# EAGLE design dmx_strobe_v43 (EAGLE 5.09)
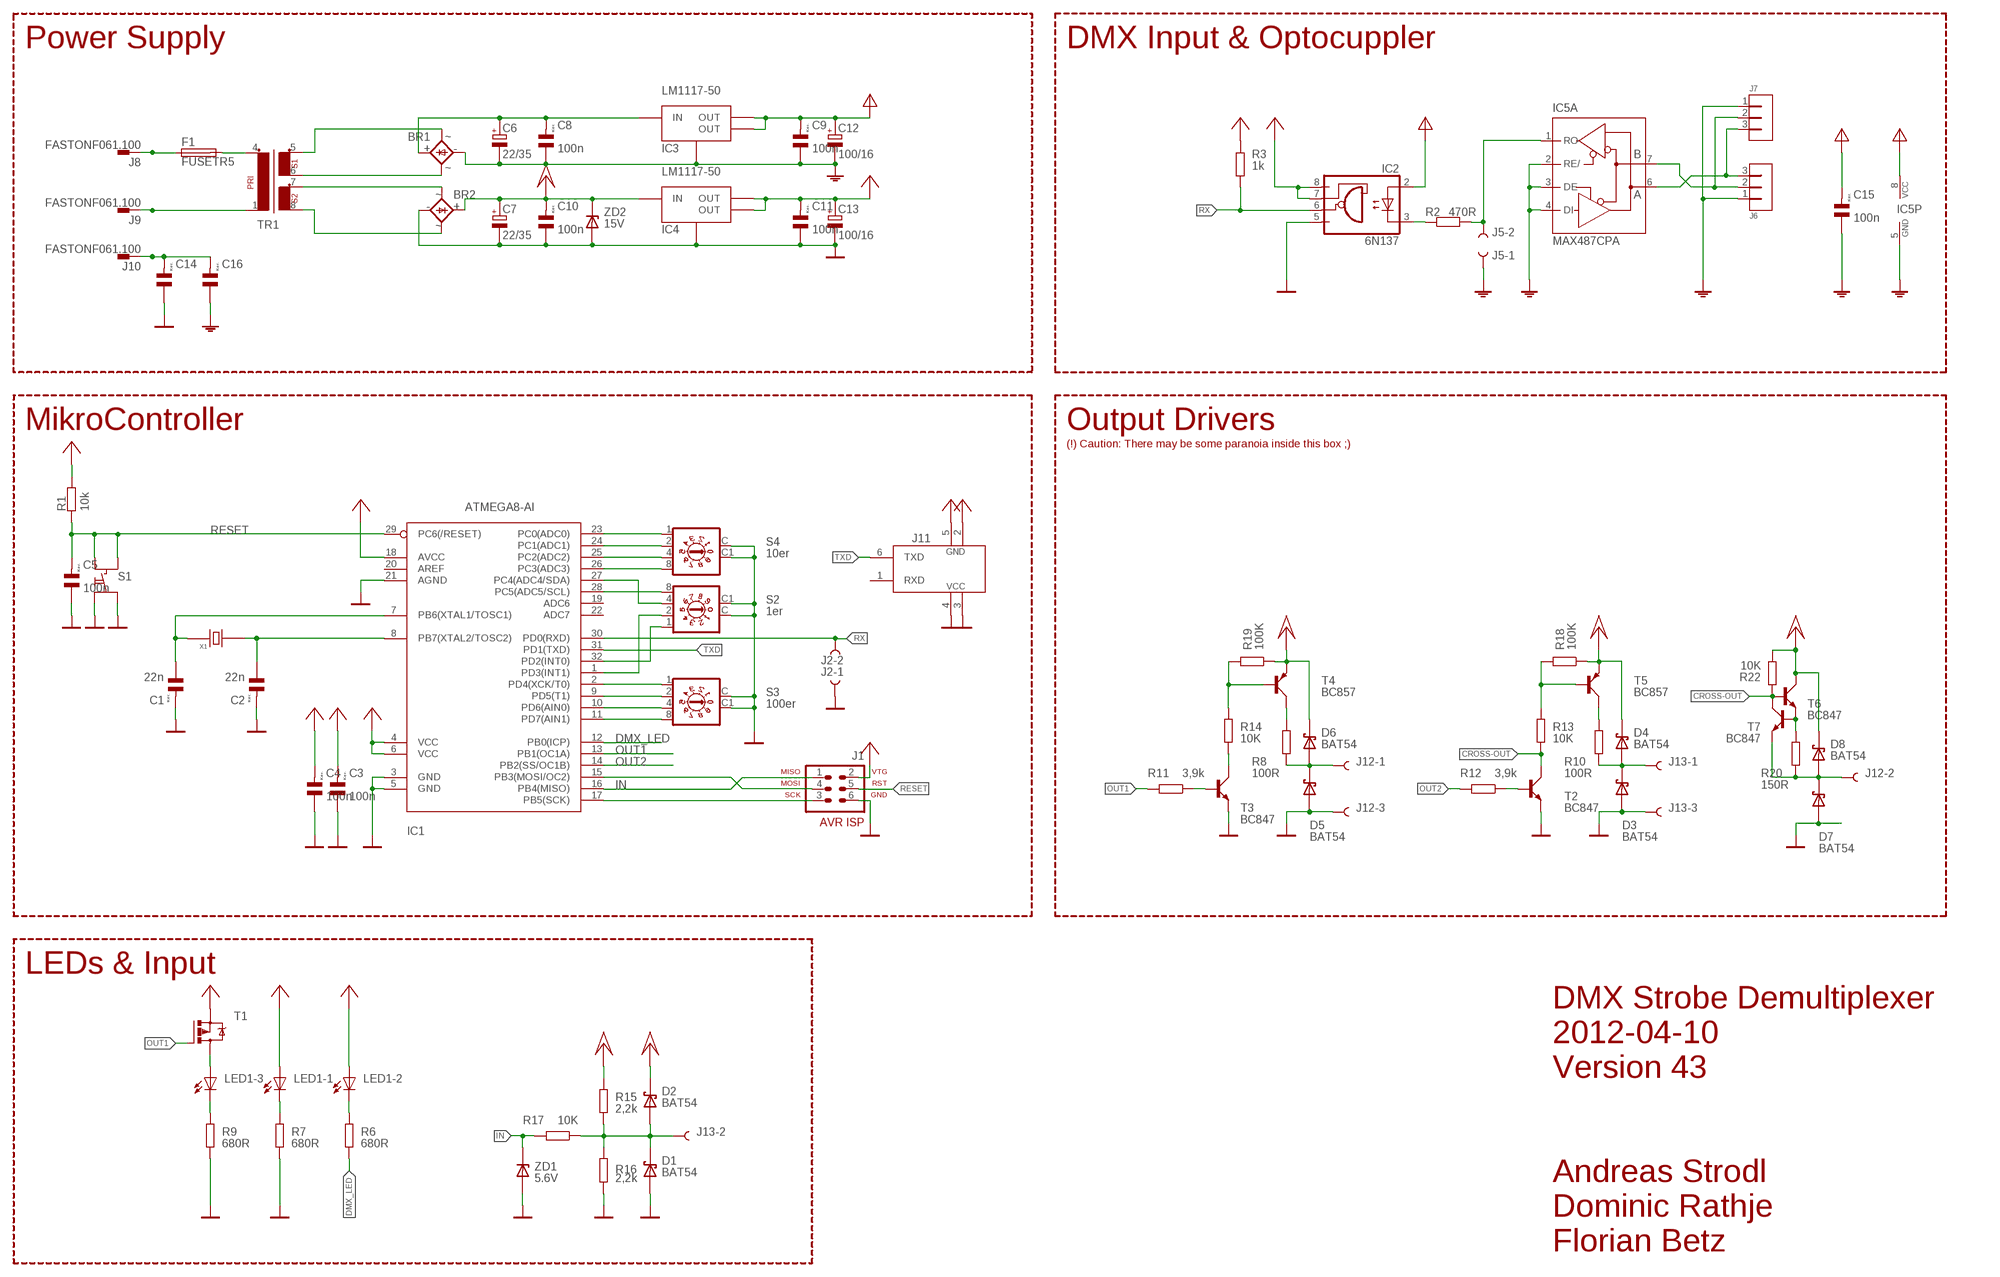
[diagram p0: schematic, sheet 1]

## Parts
BR1  BRÜCKE_DIL  [BRÜCKE_DIL]
BR2  BRÜCKE_DIL  [BRÜCKE_DIL]
C1  22n  C_KER_0805  [C0805K]
C2  22n  C_KER_0805  [C0805K]
C3  100n  C_KER_0805  [C0805K]
C4  100n  C_KER_0805  [C0805K]
C5  100n  C_KER_0805  [C0805K]
C6  22/35  ELKO_SMD_06  [153CLV-0605]
C7  22/35  ELKO_SMD_06  [153CLV-0605]
C8  100n  C_KER_0805  [C0805K]
C9  100n  C_KER_0805  [C0805K]
C10  100n  C_KER_0805  [C0805K]
C11  100n  C_KER_0805  [C0805K]
C12  100/16  ELKO_SMD_06  [153CLV-0605]
C13  100/16  ELKO_SMD_06  [153CLV-0605]
C14  C_KER_5,0  [K5,0]
C15  100n  C_KER_0805  [C0805K]
C16  C_KER_5,0  [K5,0]
D1  BAT54  SCHOTTKY-DIODE-SOD323  [SOD323-W]
D2  BAT54  SCHOTTKY-DIODE-SOD323  [SOD323-W]
D3  BAT54  SCHOTTKY-DIODE-SOD323  [SOD323-W]
D4  BAT54  SCHOTTKY-DIODE-SOD323  [SOD323-W]
D5  BAT54  SCHOTTKY-DIODE-SOD323  [SOD323-W]
D6  BAT54  SCHOTTKY-DIODE-SOD323  [SOD323-W]
D7  BAT54  SCHOTTKY-DIODE-SOD323  [SOD323-W]
D8  BAT54  SCHOTTKY-DIODE-SOD323  [SOD323-W]
F1  FUSETR5  [TR5]
IC1  ATMEGA8-AI  [TQFP32-08]
IC2  6N137  [DIL08]
IC3  LM1117-50  [SOT223]
IC4  LM1117-50  [SOT223]
IC5  MAX487CPA  MAX485CPA  [DIL08]
J1  AVR-ISP-6HG  [ML6]
J2  SL2S_1X2G_254  [SL1X2G_254]
J5  SL2S_1X2G_254  [SL1X2G_254]
J6  SL3_MOLEX  [MOLEX3]
J7  SL3_MOLEX  [MOLEX3]
J8  FASTONF061.100  [F061.100]
J9  FASTONF061.100  [F061.100]
J10  FASTONF061.100  [F061.100]
J11  RS232_6PINHG  [ML6]
J12  SL3S_MOLEX  [MOLEX3]
J13  SL3S_MOLEX  [MOLEX3]
LED1  GELB  DUAL_LED  [DUAL_LED]
R1  10k  R_0805  [R0805]
R2  470R  R_0805  [R0805]
R3  1k  R_0805  [R0805]
R6  680R  R_0805  [R0805]
R7  680R  R_0805  [R0805]
R8  100R  R_0805  [R0805]
R9  680R  R_0805  [R0805]
R10  100R  R_0805  [R0805]
R11  3,9k  R_0805  [R0805]
R12  3,9k  R_0805  [R0805]
R13  10K  R_0805  [R0805]
R14  10K  R_0805  [R0805]
R15  2,2k  R_0805  [R0805]
R16  2,2k  R_0805  [R0805]
R17  10K  R_0805  [R0805]
R18  100K  R_0805  [R0805]
R19  100K  R_0805  [R0805]
R20  150R  R_0805  [R0805]
R22  10K  R_0805  [R0805]
S1  PHAP3301  [TASTER3301]
S2  1er  DRS3010  [DRR3010]
S3  100er  DRS3010  [DRR3010]
S4  10er  DRS3010  [DRR3010]
T1  P-FET-SOT23  [SOT23]
T2  BC847  NPN_SOT23  [SOT23]
T3  BC847  NPN_SOT23  [SOT23]
T4  BC857  PNP_SOT23  [SOT23]
T5  BC857  PNP_SOT23  [SOT23]
T6  BC847  NPN_SOT23  [SOT23]
T7  BC847  NPN_SOT23  [SOT23]
TR1  EE20-2  [EE20-2]
X1  CRYSTAL-HC49U-S  [HC49U-S]
ZD1  5.6V  Z-DIODE_MINIMELF  [MINIMELF]
ZD2  15V  Z-DIODE_SOD323  [SOD323-W]

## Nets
AGND: BR1.- C6.- C8.1 C9.1 C12.- C15.1 C16.P$1 IC3.1(GND) IC5.2(A:RE/) IC5.3(A:DE) IC5.4(A:DI) IC5.5(P:GND) J5.1 J6.1 J7.1
AVCC: C9.2 C12.+ C15.2 IC2.2(A) IC3.2(OUT) IC3.4(OUT) IC5.8(P:VCC)
CROSS-OUT: R13.1 R22.2 T2.3(C) T6.1(B) T7.3(C)
DMX_LED: IC1.12(PB0(ICP)) R6.1
GND: BR2.- C1.2 C2.2 C3.1 C4.1 C5.1 C7.- C10.1 C11.1 C13.- C14.P$1 D1.A D3.A D5.A D7.A IC1.3(GND) IC1.5(GND) IC1.21(AGND) IC2.5(GND) IC4.1(GND) J1.6 J2.1 J11.3(VCC) J11.4(VCC) J12.3 J13.3 R7.1 R9.1 R16.1 S1.3 S1.4 S2.C S2.C1(C) S3.C S3.C1(C) S4.C S4.C1(C) T2.2(E) T3.2(E) ZD1.A ZD2.A
H: IC5.7(A:B) J6.2 J7.2
IN: IC1.16(PB4(MISO)) J1.1 R17.2 ZD1.C
L: IC5.6(A:A) J6.3 J7.3
N$1: C2.1 IC1.8(PB7(XTAL2/TOSC2)) X1.1
N$2: C1.1 IC1.7(PB6(XTAL1/TOSC1)) X1.2
N$3: IC1.17(PB5(SCK)) J1.3
N$4: IC5.1(A:RO) J5.2 R2.2
N$5: IC1.15(PB3(MOSI/OC2)) J1.4
N$6: IC2.3(C) R2.1
N$11: IC1.23(PC0(ADC0)) S4.1
N$12: BR1.AC2 TR1.6
N$13: BR2.AC1 TR1.7
N$14: BR2.AC2 TR1.8
N$15: BR1.AC1 TR1.5
N$16: BR1.+ C6.+ C8.2 IC3.3(IN)
N$17: R10.2 T5.3(C)
N$18: IC1.24(PC1(ADC1)) S4.2
N$19: IC1.25(PC2(ADC2)) S4.4
N$20: IC1.26(PC3(ADC3)) S4.8
N$21: IC1.11(PD7(AIN1)) S3.8
N$22: IC1.10(PD6(AIN0)) S3.4
N$23: IC1.9(PD5(T1)) S3.2
N$24: IC1.2(PD4(XCK/T0)) S3.1
N$25: IC1.28(PC5(ADC5/SCL)) S2.8
N$26: IC1.27(PC4(ADC4/SDA)) S2.4
N$27: IC1.32(PD2(INT0)) S2.1
N$28: IC1.1(PD3(INT1)) S2.2
N$29: LED1.K3(-3:C) R9.2
N$30: LED1.A3(-3:A) T1.3(D)
N$31: R20.2 T6.2(E) T7.1(B)
N$32: D7.C D8.A J12.2 R20.1 T7.2(E)
N$33: LED1.K1(-1:C) R7.2
N$34: LED1.K2(-2:C) R6.2
N$35: R12.1 T2.1(B)
N$36: R11.1 T3.1(B)
N$37: F1.1 J8.A1 J8.A2(1.1)
N$38: F1.2 TR1.4
N$39: J9.A1 J9.A2(1.1) TR1.1
N$40: C14.P$2 C16.P$2 J10.A1 J10.A2(1.1)
N$41: D3.C D4.A J13.1 R10.1
N$42: R13.2 R18.2 T5.1(B)
N$45: D5.C D6.A J12.1 R8.1
N$46: R8.2 T4.3(C)
N$47: R14.1 T3.3(C)
N$48: R14.2 R19.2 T4.1(B)
N$49: D1.C D2.A J13.2 R15.1 R16.2 R17.1
OUT1: IC1.13(PB1(OC1A)) R11.2 T1.1(G)
OUT2: IC1.14(PB2(SS/OC1B)) R12.2
RESET: C5.2 IC1.29(PC6(/RESET)) J1.5 R1.1 S1.1 S1.2
RX: IC1.30(PD0(RXD)) IC2.6(VO) J2.2 R3.2
TXD: IC1.31(PD1(TXD)) J11.6(TXD)
VCC: C3.2 C4.2 C11.2 C13.+ IC1.4(VCC) IC1.6(VCC) IC1.18(AVCC) IC2.7(VE) IC2.8(VCC) IC4.2(OUT) IC4.4(OUT) J1.2 J11.2(GND) J11.5(GND) LED1.A1(-1:A) LED1.A2(-2:A) R1.2 R3.1 T1.2(S)
VDD: BR2.+ C7.+ C10.2 D2.C D4.C D6.C D8.C IC4.3(IN) R15.2 R18.1 R19.1 R22.1 T4.2(E) T5.2(E) T6.3(C) ZD2.C
Unconnected: IC1.19(ADC6) IC1.20(AREF) IC1.22(ADC7) J11.1(RXD)

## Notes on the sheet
- Power Supply | DMX Input & Optocuppler
- MikroController | Output Drivers
- (!) Caution: There may be some paranoia inside this box ;)
- LEDs & Input
- DMX Strobe Demultiplexer
- 2012-04-10
- Version 43
- Andreas Strodl
- Dominic Rathje
- Florian Betz

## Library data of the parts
BR1 BR2 = lib-halbleiter:BRÜCKE: RECTIFIER grid 5,08 x 5,08 mm
C1-C5 C8-C11 C14-C16 = lib-rcl:C_KER
C6 C7 C12 C13 = lib-rcl:ELKO
D1-D8 = lib-halbleiter:SCHOTTKY-DIODE
F1 = fuse:FUSE: Fuse
IC1 = lib-avr:ATMEGA8: MICROCONTROLLER 8 Kbytes FLASH 1 kbytes SRAM 512 bytes EEPROM USART 6-channel 10 bit ADC 2-channel 8 bit ADC
IC2 = lib-halbleiter:6N137
IC3 IC4 = lib-ic:LM1117-*: Alternativ auch TLV1117 von TI
IC5 = lib-ic:MAX485
J1 = lib-avr:AVR-ISP-6: AVR ISP-6 Serial Programming Header
J2 J5 = lib-connectors:SL2S?
J6 J7 = lib-connectors:SL3?
J8-J10 = lib-connectors:FASTON: Flachstecker Typ Tyco/Electronics/AMP TAB, FASTON
J11 = lib-com:RS232_6PIN
J12 J13 = lib-connectors:SL3S?
LED1 = lib-halbleiter:DUAL_LED
R1-R3 R6-R20 R22 = lib-rcl:R: RESISTOR, European symbol
S1 = lib-switch:PHAP?*
S2-S4 = lib-switch:DRS3010: DIL/CODE SWITCH
T1 = lib-halbleiter:P-FET
T2 T3 T6 T7 = lib-halbleiter:NPN
T4 T5 = lib-halbleiter:PNP
TR1 = trafo:EE20-2: TRANSFORMER 1 primary winding, 2 secondary windings ERA
X1 = lib-misc:CRYSTAL
ZD1 ZD2 = lib-halbleiter:Z-DIODE

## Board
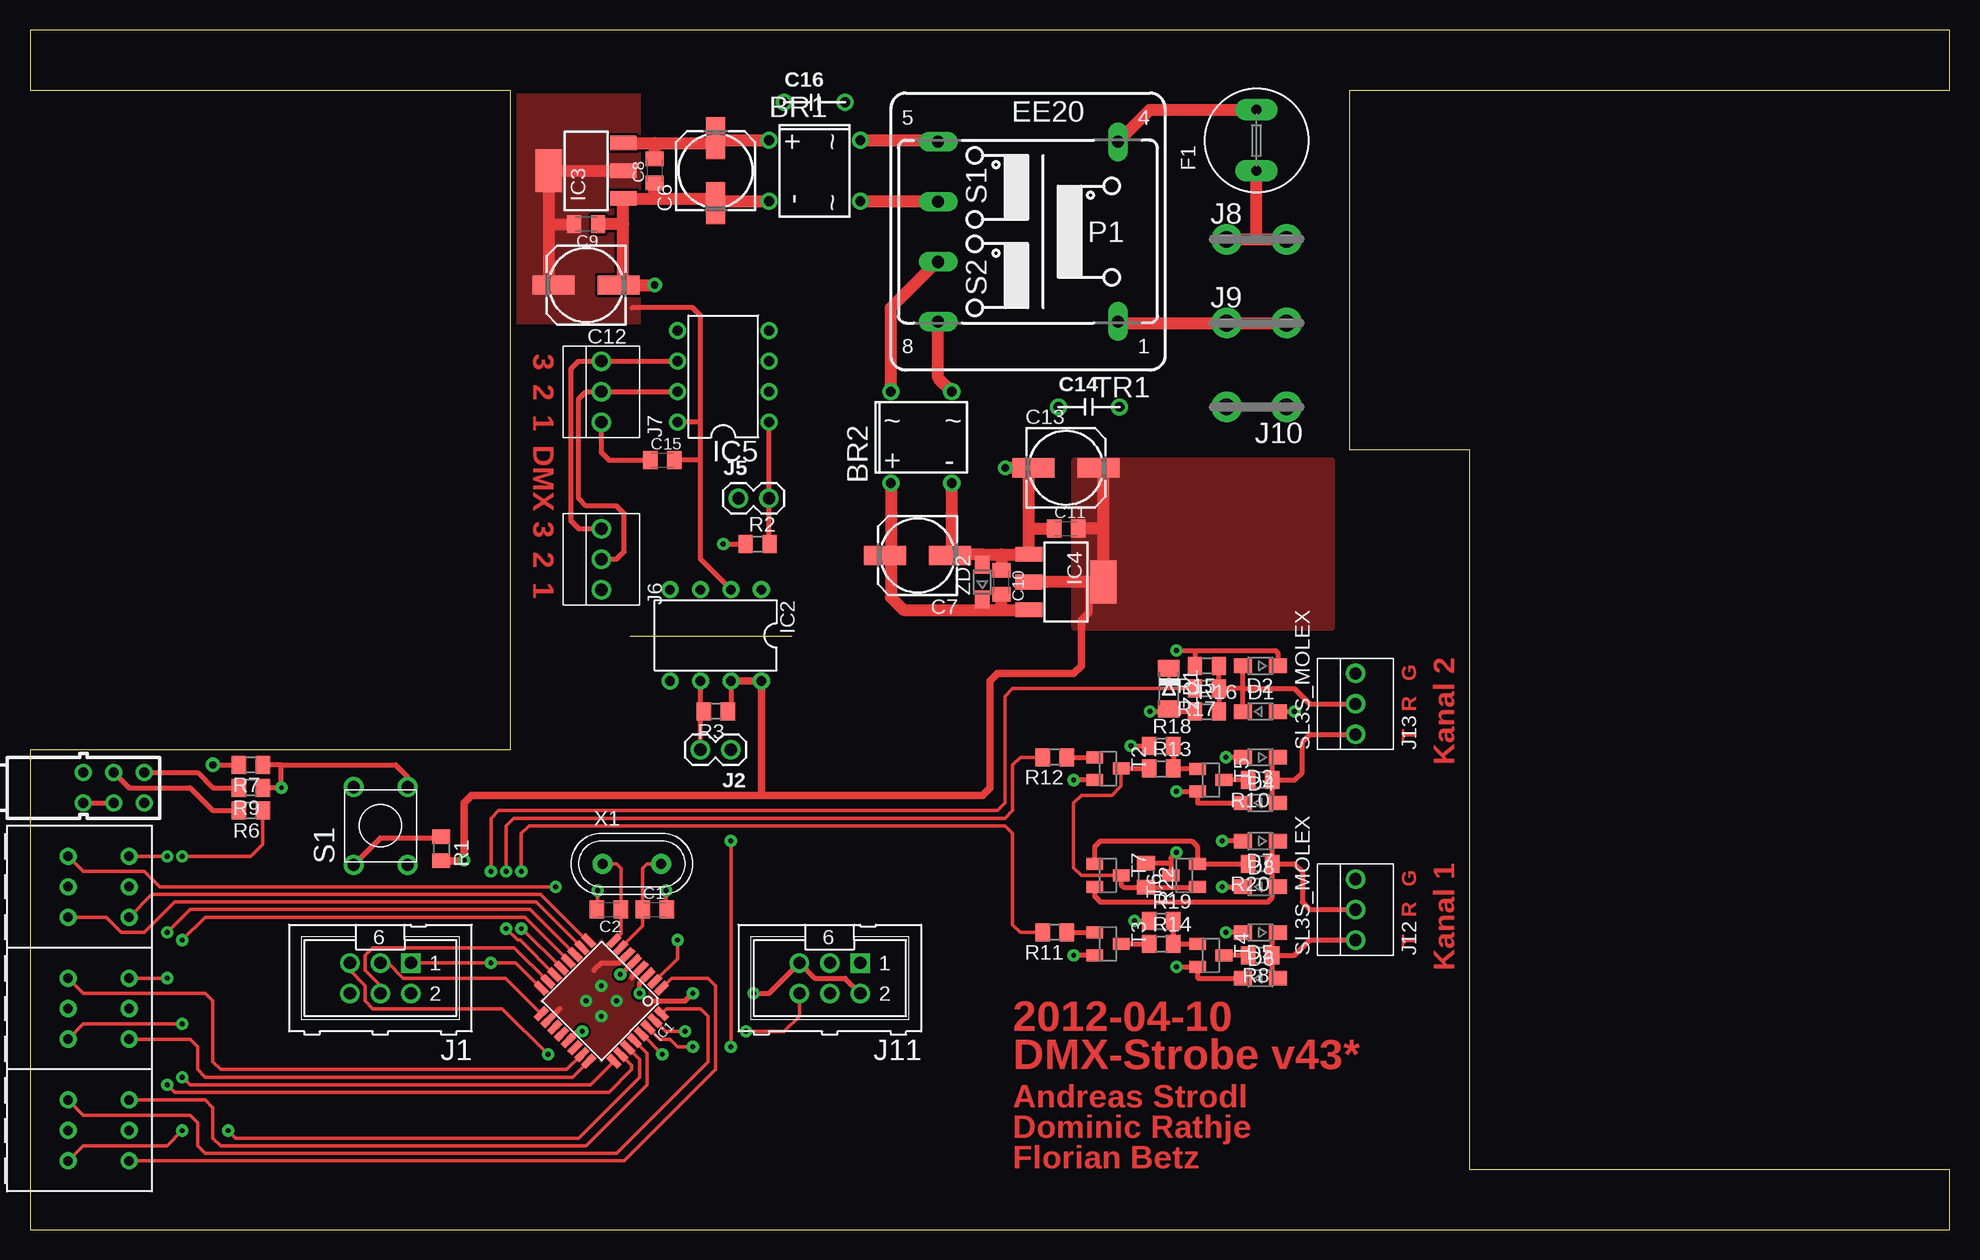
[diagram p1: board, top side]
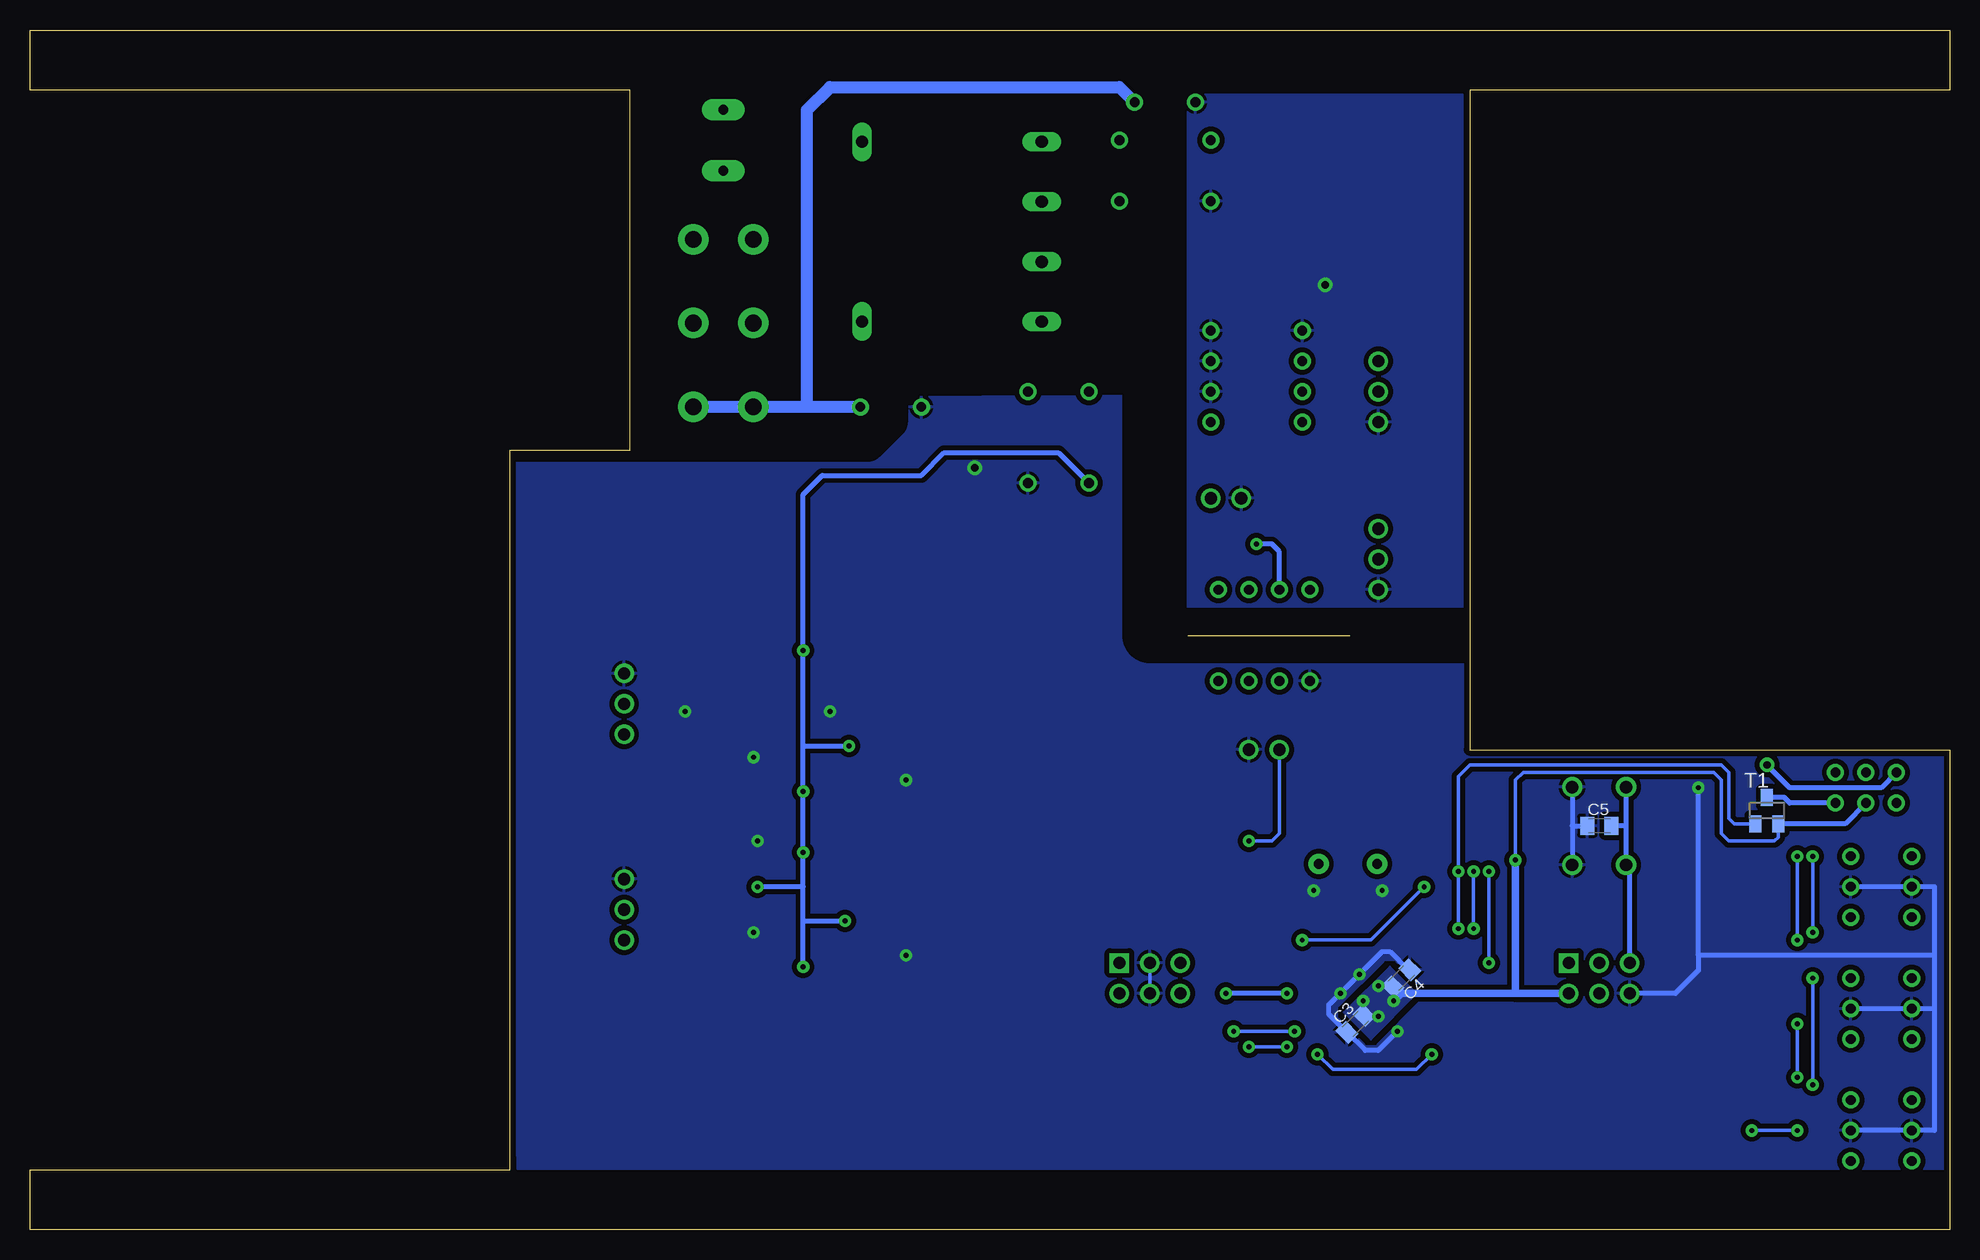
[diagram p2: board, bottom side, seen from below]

Size 160.02 x 100 mm. Coordinates in mm from the lower left corner, seen from the top.
Outline: 50,49.5 63.5,49.5
Outline: 0,0 160,0 160.02,5 120,5 120,65 110,65 110,95 160,95 160,100 0,100 0,95 40,95 40,40 0,40 0,0
Copper layers (1*16): Top 0.0381mm / dielectric 1.4986mm / Bottom 0.0381mm
Design rules "uni_ulm": minimum track width 8mil, minimum drill 16mil, track to track 8mil, track to pad 8mil, pad to pad 8mil, via to via 8mil, smd to smd 8mil, copper to edge 20mil, drill to drill 8mil, minimum pad ring 12mil, minimum via ring 12mil, stop-mask expansion 4mil, vias tented up to drill 24mil, thermal gap 10mil
bRestrict: 5 lines

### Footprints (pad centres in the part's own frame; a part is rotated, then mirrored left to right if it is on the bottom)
BRÜCKE_DIL = drill 0.813 pad 1.422 round: + -2.54,-3.81; - 2.54,-3.81; AC1 -2.54,3.81; AC2 2.54,3.81
C0805K = smd 1.2 x 1.5: 1 -1,0; 2 1,0
153CLV-0605 = smd 3.5 x 1.6: + 2.7,0; - -2.7,0
K5,0 = drill 0.813 pad 1.422 round: P$1 -2.54,0; P$2 2.54,0
SOD323-W = smd 1.5 x 1.2: A 1.45,0; C -1.45,0
TR5 = drill 0.813 pad 1.778 long: 1 -2.54,0; 2 2.54,0
TQFP32-08 = smd 1.27 x 0.559: 1 -4.293,2.8; 2 -4.293,2; 3 -4.293,1.2; 4 -4.293,0.4; 5 -4.293,-0.4; 6 -4.293,-1.2; 7 -4.293,-2; 8 -4.293,-2.8; 17 4.293,-2.8; 18 4.293,-2; 19 4.293,-1.2; 20 4.293,-0.4; 21 4.293,0.4; 22 4.293,1.2; 23 4.293,2; 24 4.293,2.8 | smd 0.559 x 1.27: 9 -2.8,-4.293; 10 -2,-4.293; 11 -1.2,-4.293; 12 -0.4,-4.293; 13 0.4,-4.293; 14 1.2,-4.293; 15 2,-4.293; 16 2.8,-4.293; 25 2.8,4.293; 26 2,4.293; 27 1.2,4.293; 28 0.4,4.293; 29 -0.4,4.293; 30 -1.2,4.293; 31 -2,4.293; 32 -2.8,4.293
DIL08 = drill 0.813 pad 1.422 round: 1 -3.81,-3.81; 2 -1.27,-3.81; 3 1.27,-3.81; 4 3.81,-3.81; 5 3.81,3.81; 6 1.27,3.81; 7 -1.27,3.81; 8 -3.81,3.81
SOT223 = smd 1.219 x 2.235: 1 -2.311,-3.099; 2 0,-3.099; 3 2.311,-3.099 | smd 3.6 x 2.2: 4 0,3.099
ML6 = drill 1.016 pad 1.626 square: 1 -2.54,-1.27 | drill 1.016 pad 1.626 round: 2 -2.54,1.27; 3 0,-1.27; 4 0,1.27; 5 2.54,-1.27; 6 2.54,1.27
SL1X2G_254 = drill 1.016 pad 1.626 round: 1 -1.27,0; 2 1.27,0
MOLEX3 = drill 1.016 pad 1.626 round: 1 -2.54,0; 2 0,0; 3 2.54,0
F061.100 = drill 1.4 pad 2.54 round: A1 -2.5,0; A2 2.5,0
DUAL_LED = drill 0.813 pad 1.422 round: A1 1.27,0; A2 1.27,2.54; A3 1.27,5.08; K1 -1.27,0; K2 -1.27,2.54; K3 -1.27,5.08
R0805 = smd 1.2 x 1.5: 1 -1,0; 2 1,0
TASTER3301 = drill 1.016 pad 1.676 round: 1 -2.235,-3.251; 2 -2.235,3.226; 3 2.261,-3.251; 4 2.261,3.226
DRR3010 = drill 0.813 round: 1 -2.54,0; 2 2.54,5.08; 4 2.54,0; 8 -2.54,5.08; C 0,5.08; C1 0,0
SOT23 = smd 1 x 1.4: 1 -0.95,-1.1; 2 0.95,-1.1; 3 0,1.1
EE20-2 = drill 1.016 long: 1 -7.493,7.493; 4 -7.493,-7.493; 5 7.493,-7.493; 6 7.493,-2.515; 7 7.493,2.515; 8 7.493,7.493
HC49U-S = drill 0.813 pad 1.676 round: 1 -2.44,0; 2 2.44,0
MINIMELF = smd 1.4 x 1.8: A 1.7,0; C -1.7,0

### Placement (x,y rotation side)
BR1  65.41,88.27 270 top
BR2  74.3,66.04 0 top
C1  52.07,26.67 0 top
C2  48.26,26.67 180 top
C3  49.53,17.14 45 bottom
C4  45.72,20.95 225 bottom
C5  29.21,33.66 0 bottom
C6  57.15,88.27 90 top
C7  73.98,56.2 180 top
C8  52.07,88.27 90 top
C9  46.35,83.82 180 top
C10  80.96,53.98 270 top
C11  86.36,58.42 0 top
C12  46.35,78.74 180 top
C13  86.36,63.5 0 top
C14  88.27,68.58 0 top
C15  52.7,64.14 0 top
C16  65.41,93.98 0 top
D1  102.55,43.18 0 top
D2  102.55,46.99 180 top
D3  102.55,39.37 180 top
D4  102.55,35.56 0 top
D5  102.55,24.77 180 top
D6  102.55,20.95 0 top
D7  102.55,32.38 180 top
D8  102.55,28.57 0 top
F1  102.23,90.81 90 top
IC1  47.62,19.05 225 top
IC2  57.15,49.53 180 top
IC3  46.35,88.27 90 top
IC4  86.36,53.98 270 top
IC5  57.78,71.12 90 top
J1  29.21,20.95 180 top
J2  57.15,40.01 180 top
J5  60.33,60.96 0 top
J6  47.62,55.88 90 top
J7  47.62,69.85 90 top
J8  102.23,82.55 0 top
J9  102.23,75.56 0 top
J10  102.23,68.58 180 top
J11  66.67,20.95 180 top
J12  110.49,26.67 90 top
J13  110.49,43.81 90 top
LED1  4.45,36.83 270 top
R1  34.29,31.75 270 top
R2  60.64,57.15 0 top
R3  57.15,43.18 180 top
R6  18.41,34.92 180 top
R7  18.41,38.73 180 top
R8  102.55,22.86 180 top
R9  18.41,36.83 180 top
R10  102.55,37.47 180 top
R11  85.41,24.77 180 top
R12  85.41,39.37 180 top
R13  94.3,38.42 0 top
R14  94.3,23.81 0 top
R15  98.11,46.99 180 top
R16  98.11,43.18 0 top
R17  98.11,45.09 180 top
R18  94.3,40.32 0 top
R19  94.3,25.72 0 top
R20  102.55,30.48 180 top
R22  93.03,29.53 270 top
S1  29.21,33.66 0 top
S2  3.17,8.26 270 top
S3  3.17,28.57 270 top
S4  3.17,18.41 270 top
T1  15.24,34.92 0 bottom
T2  89.85,38.42 270 top
T3  89.85,23.81 270 top
T4  98.42,22.86 270 top
T5  98.42,37.47 270 top
T6  96.2,29.53 90 top
T7  89.85,29.53 270 top
TR1  83.19,83.19 180 top
X1  50.16,30.48 0 top
ZD1  94.93,45.09 270 top
ZD2  79.38,53.98 90 top

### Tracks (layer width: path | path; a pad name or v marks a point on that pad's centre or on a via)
AGND  (via drill 0.61 pad 0.81)
  Top 0.406: C15.1 48.26,64.14 47.62,64.77 J7.1
  Top 1.016: BR1.- 57.31,85.72 C6.- 56.76,85.95 52.07,85.95 | 52.07,85.95 IC3.1 49.45,83.82 | 52.07,85.95 C8.1 | 49.45,83.82 49.45,79.14 C12.- v52.07,78.74 | 49.45,83.82 C9.1
  pour Bottom (isolate 0.406): 40.64,94.61 40.64,49.53 63.5,49.53 63.5,94.61
AVCC
  Top 0.406: IC2.2 55.88,55.88 55.88,64.14 | 55.88,64.14 55.88,67.31 | 55.88,67.31 IC5.8 | 55.88,67.31 55.88,76.2 55.24,76.83 50.16,76.83 | 55.88,64.14 C15.2
  Top 1.016: IC3.2 IC3.4 43.26,83.82 | 43.26,83.82 43.26,79.14 C12.+ | 43.26,83.82 C9.2
  pour Top (isolate 0.203, no thermals): 40.64,94.61 40.64,75.56 50.8,75.56 50.8,94.61
CROSS-OUT
  Top 0.305: T7.3 87.63,29.53 87,30.16 87,35.56 87.63,36.2 90.17,36.2 90.95,36.98 T2.3
  Top 0.406: T7.3 90.95,28.75 91.17,28.53 R22.2 97.25,28.53 T6.1 | T2.3 R13.1
DMX_LED  (via drill 0.41 pad 0.81)
  Top 0.305: IC1.12 44.87,22.44 41.27,26.04 14.61,26.04 v12.7,24.13 | v12.7,31.11 18.41,31.11 19.41,32.12 R6.1
  Bottom 0.305: v12.7,24.13 v12.7,31.11
GND  (via drill 0.41 pad 0.81, 0.61 pad 0.81)
  Top 0.305: C2.2 47.31,26.67 v47.31,28.26 | C1.2 53.02,26.67 v53.02,28.26
  Top 0.406: 20.95,38.73 R7.1 | R9.1 v20.95,36.83 20.95,38.73 | IC1.5 49.28,21.27 v49.21,21.27 | IC1.21 45.65,16.51 v46.04,16.51 | 20.95,38.73 30.48,38.73 31.47,37.74 S1.4 | IC1.3 50.8,20.53 v50.8,19.68 | T3.2 v87,22.86 | T2.2 v87,37.47 | D3.A v99.69,39.37 | D5.A v99.69,24.77 | D7.A v99.38,32.38 | ZD1.A 94.93,43.18 R16.1 v93.34,43.18 | D1.A v105.41,43.18
  Top 1.016: 83.26,58.42 IC4.1 80.96,56.29 | 83.26,58.42 83.26,63.1 C13.- v81.28,63.5 | 83.26,58.42 C11.1 | 76.83,56.52 76.83,56.35 C7.- | 76.83,56.52 BR2.- | 79.38,56.29 77.06,56.29 76.83,56.52 | 80.96,56.29 C10.1 | 79.38,56.29 80.96,56.29 | ZD2.A 79.38,56.29
  Bottom 0.305: J11.4 J11.3
  Bottom 0.406: 1.27,18.41 S4.C1 S4.C | 1.27,18.41 1.27,8.26 S2.C1 S2.C | 1.27,18.41 1.27,22.86 | 1.27,22.86 1.27,28.57 S3.C1 S3.C | C4.1 45.16,21.66 46.67,23.18 47.31,23.18 v49.21,21.27 v50.8,19.68 51.75,18.73 51.75,17.95 C3.1 48.72,14.92 47.62,14.92 v46.04,16.51 | 20.95,22.86 v20.95,36.83 | J1.6 22.86,19.68 20.95,21.59 20.95,22.86 | 1.27,22.86 20.95,22.86 | 31.47,33.66 S1.3 | S1.4 31.47,33.66 | 31.47,33.66 C5.1
  pour Bottom (isolate 0.406, rank 2): 0.64,69.85 -0.64,5.08 119.38,5.08 120.65,69.22
H
  Top 0.406: IC5.7 J7.2 46.35,69.85 45.72,69.22 45.72,60.96 46.35,60.33 48.9,60.33 49.53,59.69 49.53,56.52 48.9,55.88 J6.2
IN  (via drill 0.41 pad 0.81)
  Top 0.305: J1.1 v38.42,22.23 40.49,22.23 IC1.16 | v38.42,29.84 38.42,34.29 39.05,34.92 80.64,34.92 81.28,35.56 81.28,44.45 81.92,45.09 94.93,45.09 | 94.93,45.09 R17.2 | 94.93,45.09 ZD1.C
  Bottom 0.305: v38.42,22.23 v38.42,29.84
L
  Top 0.406: J6.3 45.72,58.42 45.09,59.05 45.09,71.75 45.72,72.39 J7.3 IC5.6
N$1
  Top 0.305: IC1.8 49.26,24.64 C2.1 49.26,30.11 48.9,30.48 X1.1
N$2
  Top 0.305: IC1.7 51.07,25.32 C1.1 51.07,30.11 51.44,30.48 X1.2
N$3
  Top 0.305: 42.4,17.78 IC1.17 39.65,20.95 31.11,20.95 29.84,22.23 J1.3
N$4
  Top 0.406: IC5.1 J5.2 61.59,57.2 R2.2
N$5
  Top 0.305: IC1.15 40.35,23.5 28.57,23.5 27.94,22.86 27.94,21.59 29.21,20.32 J1.4
N$6  (via drill 0.41 pad 0.81)
  Top 0.406: v57.78,57.15 R2.1
  Bottom 0.406: v57.78,57.15 56.52,57.15 55.88,56.52 IC2.3
N$11
  Top 0.305: S4.1 4.45,19.68 14.61,19.68 15.24,19.05 15.24,13.97 15.88,13.34 44.74,13.34 IC1.23
N$12
  Top 1.016: BR1.AC2 75.67,85.72 TR1.6
N$13
  Top 1.016: TR1.7 75.59,80.67 71.75,76.83 BR2.AC1
N$14
  Top 1.016: TR1.8 75.69,70.99 BR2.AC2
N$15
  Top 1.016: BR1.AC1 75.56,90.81 TR1.5
N$16
  Top 1.016: BR1.+ 57.31,90.81 C6.+ 56.76,90.58 52.07,90.58 | IC3.3 52.07,90.58 | 52.07,90.58 C8.2
N$17
  Top 0.406: R10.2 T5.3
N$18
  Top 0.305: S4.2 13.34,15.88 13.97,15.24 13.97,13.34 14.61,12.7 45.23,12.7 IC1.24
N$19  (via drill 0.41 pad 0.81)
  Top 0.305: S4.4 4.45,17.14 v12.7,17.14 | IC1.25 46.71,12.06 13.34,12.06 v12.7,12.7
  Bottom 0.305: v12.7,17.14 v12.7,12.7
N$20  (via drill 0.41 pad 0.81)
  Top 0.305: IC1.26 50.16,13.68 50.16,13.34 48.26,11.43 12.06,11.43 v11.43,12.06 | v11.43,20.95 S4.8
  Bottom 0.305: v11.43,12.06 v11.43,20.95
N$21  (via drill 0.41 pad 0.81)
  Top 0.305: IC1.11 41.7,26.67 13.34,26.67 v11.43,24.77 | v11.43,31.11 S3.8
  Bottom 0.305: v11.43,24.77 v11.43,31.11
N$22
  Top 0.305: IC1.10 42.2,27.3 12.06,27.3 9.53,24.77 7.62,24.77 6.35,26.04 S3.4
N$23
  Top 0.305: IC1.9 46.42,24.07 42.55,27.94 10.16,27.94 S3.2
N$24  (via drill 0.41 pad 0.81)
  Top 0.305: S3.1 4.45,29.84 9.53,29.84 10.79,28.57 v43.81,28.57 | IC1.2 53.98,22.57 v53.98,24.13
  Bottom 0.305: v53.98,24.13 48.26,24.13 v43.81,28.57
N$25
  Top 0.305: IC1.28 51.44,14.67 51.44,12.06 46.35,6.99 15.88,6.99 15.24,7.62 15.24,10.16 14.61,10.79 S2.8
N$26  (via drill 0.41 pad 0.81)
  Top 0.305: S2.4 4.45,6.99 11.43,6.99 v12.7,8.26 | IC1.27 50.8,14.18 50.8,12.7 45.72,7.62 17.14,7.62 v16.51,8.26
  Bottom 0.305: v12.7,8.26 v16.51,8.26
N$27
  Top 0.305: S2.1 4.45,9.53 13.34,9.53 13.97,8.89 13.97,6.99 14.61,6.35 48.9,6.35 56.52,13.97 56.52,17.78 55.88,18.41 53.06,18.41 IC1.32
N$28
  Top 0.305: IC1.1 53.49,20.95 56.52,20.95 57.15,20.32 57.15,13.34 49.53,5.71 S2.2
N$29
  Top 0.406: LED1.K3 13.97,38.1 15.24,36.83 R9.2
N$30
  Bottom 0.406: T1.3 13.8,36.02 13.34,35.56 LED1.A3
N$31
  Top 0.406: T7.1 88.75,31.92 89.22,32.38 96.84,32.38 97.3,31.92 T6.2 R20.2
N$32
  Top 0.406: R20.1 103.55,32.38 D7.C | 103.55,28.57 R20.1 | 103.55,28.57 D8.A | 103.55,28.57 103.55,27.67 103.19,27.3 89.22,27.3 88.75,27.77 T7.2 | J12.2 106.68,26.67 106.05,27.3 106.05,29.84 105.41,30.48 R20.1
N$33  (via drill 0.61 pad 0.81)
  Top 0.406: v15.24,38.73 R7.2
  Bottom 0.406: LED1.K1 5.71,36.83 13.34,36.83 v15.24,38.73
N$34
  Top 0.406: LED1.K2 8.26,36.83 13.34,36.83 15.24,34.92 R6.2
N$35
  Top 0.406: R12.1 T2.1
N$36
  Top 0.406: R11.1 T3.1
N$37
  Top 1.016: J8.A1 102.23,82.55 | 102.23,82.55 J8.A2 | 102.23,82.55 F1.1
N$38
  Top 1.016: F1.2 93.34,93.34 TR1.4
N$39
  Top 1.016: J9.A2 J9.A1 90.81,75.56 TR1.1
N$40
  Bottom 1.016: 95.25,68.58 J10.A2 J10.A1 | C14.P$2 95.25,68.58 | 95.25,68.58 95.25,93.34 93.34,95.25 69.22,95.25 C16.P$2
N$41
  Top 0.406: R10.1 103.55,35.56 D4.A | R10.1 103.55,39.37 D3.C | J13.1 106.68,41.27 106.05,40.64 106.05,38.1 105.41,37.47 R10.1
N$42
  Top 0.406: T5.1 R13.2 R18.2
N$45
  Top 0.406: R8.1 103.55,20.95 D6.A | R8.1 103.55,24.77 D5.C | J12.1 106.68,24.13 105.41,22.86 R8.1
N$46
  Top 0.406: R8.2 T4.3
N$47
  Top 0.406: T3.3 R14.1
N$48
  Top 0.406: R14.2 T4.1 | R14.2 | R14.2 R19.2
N$49
  Top 0.406: 101.1,45.09 R17.1 | 101.1,45.09 D2.A | D1.C 101.1,45.09 | J13.2 106.68,43.81 105.41,45.09 101.1,45.09 | R17.1 R16.2 | R17.1 R15.1
OUT1  (via drill 0.41 pad 0.81)
  Top 0.305: IC1.13 41.03,25.08 v40.96,25.08 | v40.96,29.84 40.96,33.02 41.59,33.66 81.28,33.66 81.92,33.02 81.92,25.4 82.55,24.77 R11.2
  Bottom 0.305: v40.96,25.08 v40.96,29.84 40.96,37.78 40.01,38.73 19.05,38.73 18.41,38.1 18.41,34.29 17.95,33.83 T1.1
OUT2  (via drill 0.41 pad 0.81)
  Top 0.305: IC1.14 40.85,24.13 40.64,24.13 v39.69,25.08 | v39.69,29.84 39.69,33.66 40.32,34.29 81.28,34.29 81.92,34.92 81.92,38.73 82.55,39.37 R12.2
  Bottom 0.305: v39.69,25.08 v39.69,29.84
RESET  (via drill 0.41 pad 0.81)
  Top 0.305: J1.5 26.67,21.59 27.94,20.32 27.94,19.05 28.57,18.41 39.37,18.41 v43.18,14.61 | IC1.29 51.01,16.3 v52.7,14.61
  Top 0.406: S1.1 29.23,32.66 34.2,32.66 R1.1
  Bottom 0.305: v52.7,14.61 51.44,13.34 44.45,13.34 v43.18,14.61
  Bottom 0.406: 26.98,33.66 S1.1 26.67,30.1 J1.5 | 26.98,33.66 S1.2 | 26.98,33.66 C5.2
RX  (via drill 0.41 pad 0.81)
  Top 0.305: IC1.30 52.5,15.88 53.34,15.88 53.98,15.24 v55.24,15.24 | v58.42,15.24 v58.42,32.38
  Top 0.406: J2.2 55.88,43.18 | 55.88,43.18 IC2.6 | 55.88,43.18 R3.2
  Bottom 0.305: v55.24,15.24 v58.42,15.24 | J2.2 55.88,33.02 56.52,32.38 v58.42,32.38
TXD  (via drill 0.41 pad 0.81)
  Top 0.305: IC1.31 52.99,16.51 v54.61,16.51 | v59.69,16.51 62.87,16.51 64.14,17.78 J11.6
  Bottom 0.305: v54.61,16.51 v59.69,16.51
VCC  (via drill 0.41 pad 0.81)
  Top 0.406: LED1.A1 LED1.A2 | IC1.6 49.1,22.23 47.62,22.23 46.99,21.59 | IC1.18 44.16,18.41 | v36.2,30.8 36.15,30.75 | J11.2 67.94,20.95 65.41,20.95 J11.5 61.59,19.68 v60.33,19.68 | IC1.4 50.16,21.02 50.16,20.95 | 52.07,19.05 54.61,19.05 v55.24,19.68 | IC2.7 58.42,43.45 R3.1
  Top 0.61: 36.15,30.75 R1.2 | 88.27,53.98 88.27,51.44 87.63,50.8 87.63,46.99 87,46.35 80.64,46.35 80.01,45.72 80.01,36.83 79.38,36.2 60.96,36.2 | v36.2,30.8 36.2,35.56 36.83,36.2 60.96,36.2 | 60.96,36.2 IC2.8 IC2.7
  Top 1.016: IC4.2 88.27,53.98 IC4.4 89.46,58.42 | 89.46,58.42 89.46,63.1 C13.+ | 89.46,58.42 C11.2
  Bottom 0.305: T1.2 14.29,32.7 14.61,32.38 18.41,32.38 19.05,33.02 19.05,37.47 19.68,38.1 35.56,38.1 36.2,37.47 v36.2,30.8
  Bottom 0.406: T1.2 8.72,33.83 LED1.A2 | v55.24,19.68 v60.33,19.68
  Bottom 0.61: 36.2,19.68 J1.2 | 36.2,19.68 45.72,19.68 v46.35,19.05 | v36.2,30.8 36.2,19.68
  other vias: 47.62,20.32 48.9,19.05 47.62,17.78
  pour Bottom (isolate 0.203, no thermals): 46.67,21.91 44.45,19.68 48.26,15.88 50.48,18.1
  pour Top (isolate 0.203, no thermals): 47.62,24.13 42.55,19.05 47.62,13.97 52.7,19.05
  pour Top (isolate 0.406, rank 2, no thermals): 87,64.14 87,50.16 108.58,50.16 108.58,64.14
VDD  (via drill 0.41 pad 0.81)
  Top 0.406: v95.57,36.51 T5.2 97.33,35.56 D4.C | v95.57,21.91 T4.2 97.33,20.95 D6.C | v91.76,40.32 R18.1 | v99.38,28.57 D8.C | D2.C 104,48.08 103.82,48.26 97.11,48.26 | 97.11,48.26 R15.2 | v95.57,48.26 97.11,48.26 | v92.08,25.72 R19.1 | 95.1,30.48 95.1,30.97 v95.57,31.43 | 95.1,30.48 T6.3 | R22.1 95.06,30.53 95.1,30.48 | 79.38,51.66 ZD2.C
  Top 1.016: 80.96,51.66 79.38,51.66 72.8,51.66 71.75,52.7 71.75,55.88 | 80.96,51.66 IC4.3 | 80.96,51.66 C10.2 | BR2.+ 71.75,55.88 | C7.+ 71.44,56.2 71.75,55.88
  Bottom 0.406: BR2.+ 74.3,64.77 83.82,64.77 85.72,62.87 93.98,62.87 95.57,61.28 v95.57,48.26 95.57,40.32 | 95.57,25.72 95.57,28.57 | 95.57,40.32 v91.76,40.32 | 95.57,40.32 v95.57,36.51 v95.57,31.43 95.57,28.57 | 95.57,28.57 v99.38,28.57 | 95.57,25.72 v92.08,25.72 | v95.57,21.91 95.57,25.72

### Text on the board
Top: 3 | 2 | 1 | DMX | 3 | 2 | 1 | G | R | T | Kanal 2 | G | R | T | Kanal 1 | 2012-04-10 | DMX-Strobe v43* | Andreas Strodl | Dominic Rathje | Florian Betz
tStop: *) Die Versionsnummer in Primzahlen absteigend, bei 43 beginnend, was in diesem Fall 1 bedeutet
bStop: 2012-04-10 | DMX-Strobe v43* | Andreas Strodl | Dominic Rathje | Florian Betz
Measures: alle Maße in mm | 0,100 | 160,100 | 0,95 | 40,95 | 110,95 | 160,95 | 110,65 | 120,65 | 50,49.5 | 63.5,49.5 | 0,40 | 40,40 | 120,5 | 160,5 | 0,0 | 160,0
